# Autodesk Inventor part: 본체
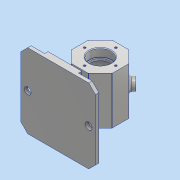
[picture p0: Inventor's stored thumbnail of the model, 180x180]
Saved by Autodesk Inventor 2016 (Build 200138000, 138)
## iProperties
Created: 2018-06
Part Number: 본체
Material: 알루미늄 6061
Document SubType Name: Modeling
Designer: 605-03
Density: 2.7 g/cm^3
Appearance: 알루미늄 - 평지
Mass: 551.998 g
Surface Area: 601.935 cm^2
Volume: 204.444 cm^3
Author: 605-03
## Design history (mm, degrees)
sketch "스케치1"
  geometry: L1 (0, 0)-(0, -62); L2 (0, -62)-(0, 30); L3 (12.426, 30)-(30, 12.426); L4 (30, 12.426)-(30, -12.426); L5 (30, -12.426)-(12.426, -30); L6 (12.426, -30)-(-12.426, -30); L7 (-12.426, -30)-(-30, -12.426); L8 (-30, -12.426)-(-30, 12.426); L9 (-30, 12.426)-(-12.426, 30); L10 (-12.426, 30)-(12.426, 30); L11 (0, 0)-(-12.426, 30); L12 (0, 0)-(12.426, 30)
  constraints: 24 end point, 2 vertical, 1 coincident, 1 midpoint, 17 other
  dimensions: "d0" = 62 distance of L1.start L1.end; "d1" = 92 distance of L1.end L2.end
extrude "돌출1" new body sketch "스케치1" distance "d2" = 70; taper "d3" = 0 deg
sketch "스케치2"
  geometry: C1 r 14 at (0, 0); 1 further point
  constraints: 1 centre point, 1 coincident
  dimensions: "d4" = 28 diameter of C1
extrude "돌출2" cut sketch "스케치2" stored distance "d5" = 70; taper "d6" = 0 deg
sketch "스케치3"
  geometry: C1 r 14 at (0, 0) reference; C2 r 16 at (0, 0)
  constraints: 1 centre point, 1 coincident
  dimensions: "d7" = 32 diameter of C2
extrude "돌출3" cut sketch "스케치3" distance "d8" = 12; taper "d9" = 0 deg
node "작업 평면1"
sketch "스케치4"
  geometry: C1 r 16 at (0, 0) reference; 1 further point
  constraints: 1 vertical alignment
  dimensions: "d10" = 23 distance of C1.centre point (0, 23)
hole "구멍1" sketch "스케치4" at (0, 23) diameter "d11" = 3.242; stored, may be unused: countersink angle "d15" = 90 deg, drill point angle "d17" = 118 deg; dims "d12" = 8, "d13" = 4, "d14" = 2, "d16" = 10
sketch "스케치5"
  geometry: C1 r 25 at (0, 0); 1 further point
  constraints: 1 centre point, 1 coincident
  dimensions: "d21" = 50 diameter of C1
extrude "돌출4" cut sketch "스케치5" stored distance "d22" = 40; taper "d23" = 0 deg
chamfer "모따기1" distance "d24" = 1; stored, may be unused: second distance "d25" = 2, angle "d26" = 45 deg
fillet "모깎기1" dims "d27" = 0.3
fillet "모깎기2" dims "d28" = 3
node "작업 평면2"
sketch "스케치6"
  geometry: L1 (67.426, 20)-(-42.574, 20); L2 (-42.574, 20)-(-42.574, -90); L3 (-42.574, -90)-(67.426, -90); L4 (67.426, -90)-(67.426, 20); L5 (-17.574, 0)-(-17.574, -70) reference; L6 (0, 0)-(0, -70) reference; L7 (0, 0)-(24.853, 0) reference; L8 (0, 0)-(0, -70) reference; L9 (24.853, -70)-(0, -70) reference; L10 (24.853, 0)-(24.853, -70) reference; L11 (37.426, -18)-(37.426, -52) reference; L12 (42.426, 0)-(42.426, -70) reference; L13 (-17.574, 0)-(-17.574, -35); 2 further points
  constraints: 10 end point, 2 midpoint, 2 parallel, 1 horizontal, 1 perpendicular, 1 vertical alignment
  dimensions: "d30" = 110 distance of L1.start L1.end; "d31" = 110 distance of L3.end L1.start; "d32" = 35 distance of L5.start L13.end; "d33" = 55 distance from line of L13.end L1
extrude "돌출5" join sketch "스케치6" distance "d34" = 5; taper "d35" = 0 deg
sketch "스케치7"
  geometry: L1 (67.426, 20)-(-42.574, 20) reference; L2 (-42.574, 20)-(-42.574, -90) reference; L3 (-42.574, -90)-(67.426, -90) reference; L4 (67.426, -90)-(67.426, 20) reference; L5 (37.426, 20)-(-12.574, 20); L6 (-12.574, 20)-(-12.574, -90); L7 (-12.574, -90)-(37.426, -90); L8 (37.426, -90)-(37.426, 20); 1 further point
  constraints: 8 end point, 2 collinear, 2 parallel, 1 horizontal, 1 perpendicular
  dimensions: "d37" = 30 distance between parallel lines of L2 L6; "d38" = 30 distance between parallel lines of L4 L8
extrude "돌출6" join sketch "스케치7" distance "d39" = 5; taper "d40" = 0 deg
sketch "스케치8"
  geometry: L1 (-42.574, 20)-(-42.574, -90) reference; L2 (-42.574, -90)-(-12.574, -90) reference; L3 (67.426, -90)-(67.426, 20) reference; L4 (37.426, -90)-(67.426, -90) reference; C1 r 5 at (-32.574, -35); C2 r 5 at (57.426, -35); 1 further point
  constraints: 2 centre point
  dimensions: "d41" = 10 distance from line of L1 C1.centre; "d42" = 55 distance from line of L2 C1.centre; "d43" = 10 diameter of C1; "d44" = 10 diameter of C2; "d45" = 10 distance from line of L3 C2.centre; "d46" = 55 distance from line of L4 C2.centre
extrude "돌출7" cut sketch "스케치8" distance "d47" = 5; taper "d48" = 0 deg
chamfer "모따기2" distance "d49" = 10; stored, may be unused: second distance "d50" = 2, angle "d51" = 45 deg
sketch "스케치9"
  geometry: L1 (37.426, 20)-(-12.574, 20) reference; L2 (12.426, -54)-(12.426, -16); L3 (7.426, -54)-(7.426, -16); L4 (17.426, -16)-(17.426, -54); A1 r 5 centre (12.426, -54) between (7.426, -54) and (17.426, -54); A2 r 5 centre (12.426, -16) between (17.426, -16) and (7.426, -16); 2 further points
  constraints: 8 end point, 4 point on circle, 4 tangent, 2 centre point, 1 midpoint, 1 parallel, 1 vertical, 1 vertical alignment
  dimensions: "d52" = 38 distance of L2.start L2.end; "d53" = 5 radius of A1; "d54" = 55 distance from line of L1 point (12.426, -35)
extrude "돌출8" join sketch "스케치9" stored distance "d55" = 5; taper "d56" = 0 deg
fillet "모깎기3" dims "d57" = 2
fillet "모깎기4" dims "d58" = 1
sketch "스케치10"
  geometry: L1 (24.024, -70)-(0, -70) reference; L2 (-17.988, 0)-(-17.988, -70) reference; 2 further points
  constraints: 1 other
  dimensions: "d59" = 35 distance from line of L1 point (12.012, -35); "d60" = 30 distance from line of L2 point (12.012, -35)
feature "엠보싱1" sketch "스케치10" dims "d61" = 0.5, "d62" = 0
node "작업 평면3"
sketch "스케치11"
  geometry: L1 (0, 0)-(21.213, 21.213); L2 (0, 0)-(0, 30); L3 (12.719, 29.707)-(29.707, 12.719) reference; L4 (-12.012, 30)-(12.012, 30) reference
  constraints: 4 end point, 2 midpoint, 1 vertical
  dimensions: "d63" = 45 deg angle of L1 L2
sketch "스케치12"
  geometry: L1 (-24.024, 70)-(0, 70) reference; L2 (0, 0)-(-24.024, 0) reference; C1 r 8 at (-12.012, 35); C2 r 4 at (-12.012, 35); 2 further points
  constraints: 2 centre point, 1 coincident, 1 midpoint, 1 vertical alignment
  dimensions: "d64" = 35 distance from line of L1 C1.centre; "d65" = 16 diameter of C1; "d66" = 8 diameter of C2
extrude "돌출9" join sketch "스케치12" distance "d67" = 7; taper "d68" = 0 deg
fillet "모깎기5" dims "d69" = 3
extrude "돌출10" cut sketch "스케치12" stored distance "d70" = 7; taper "d71" = 0 deg
chamfer "모따기3" distance "d72" = 1; stored, may be unused: second distance "d73" = 2, angle "d74" = 45 deg
node "솔리드1"
pattern_circular "원형 패턴1" dims angle "d19" = 360 deg
mirror "대칭1"
node "투영된 루프1"
other parameters: "d29" = -92
